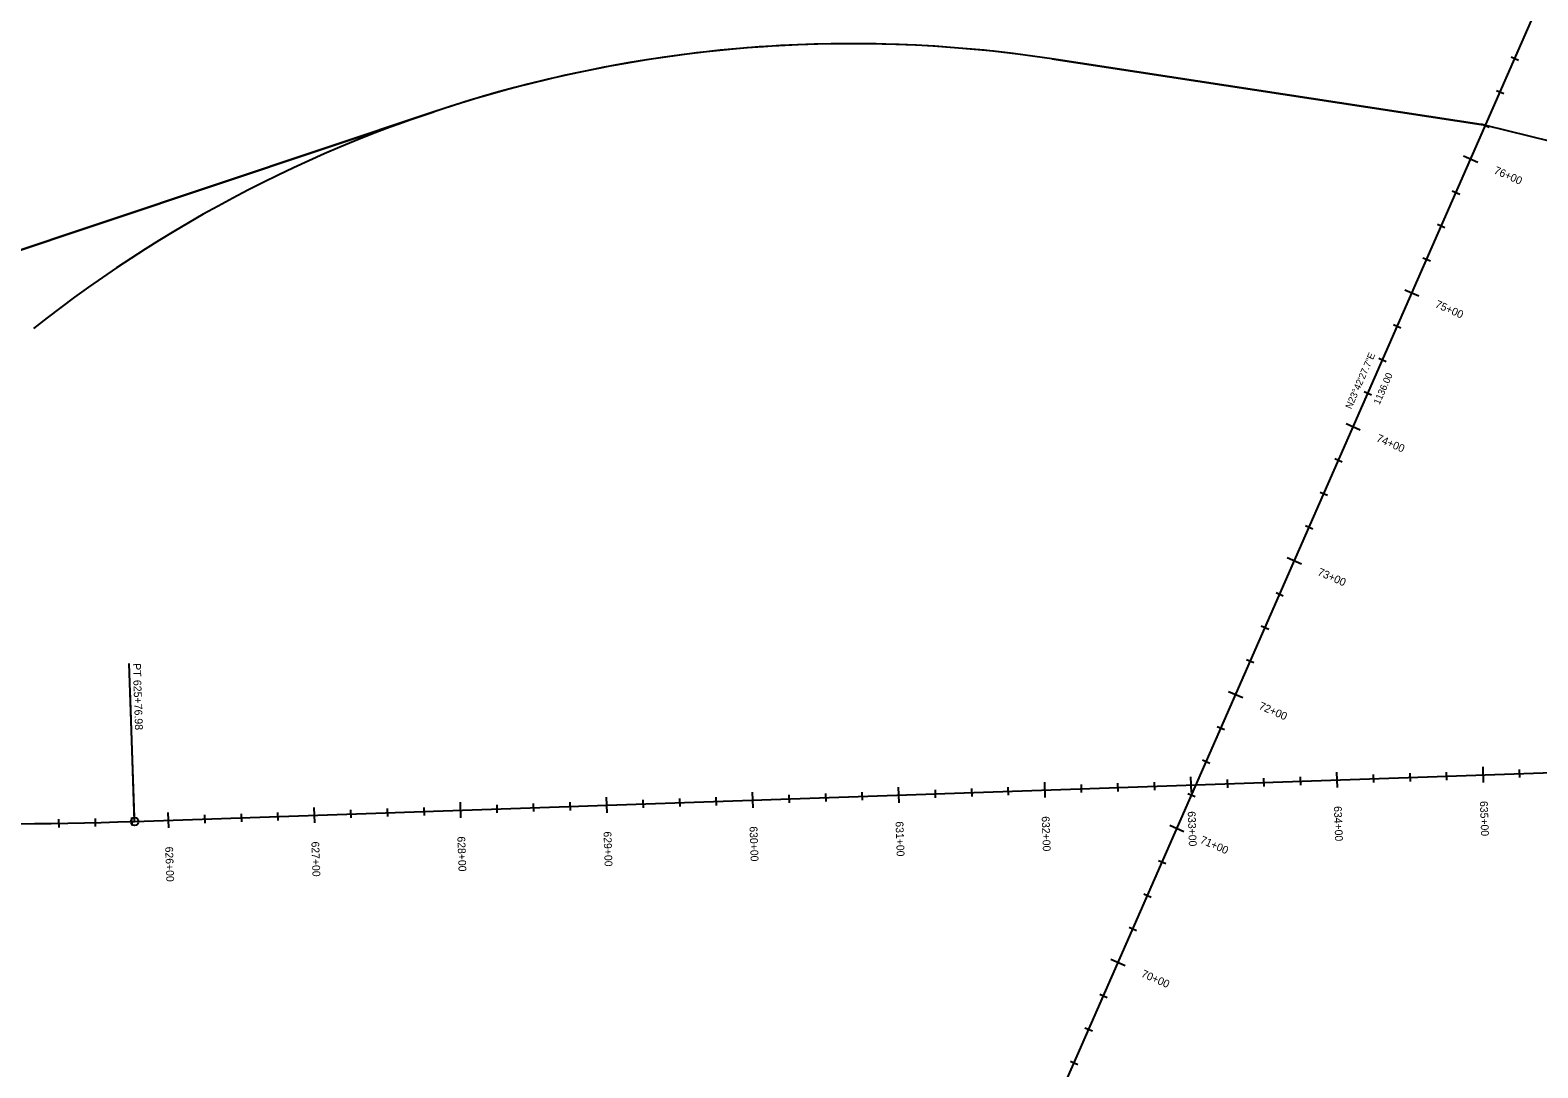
# Model space of a CAD drawing. Extents: x 2307903 to 2339201, y 758183 to 762824.
# Drawn here: x 2320206 to 2321238, y 760043 to 760752 of the extents above; entities that cross this region are included whole.
import ezdxf

# ---------------------------------------------------------------- set-up
doc = ezdxf.new("R2010")
doc.units = 0
for name, color, linetype in [('Default', 7, 'Continuous'), ('E_Terrain_Contour_Imported', 7, 'Continuous'), ('E_Terrain_Contour_Major', 7, 'Continuous'), ('E_Terrain_Flow_Arrows', 7, 'Continuous'), ('E_Terrain_Hole', 7, 'Continuous'), ('E_Terrain_Island', 7, 'Continuous'), ('E_Terrain_Points_High', 7, 'Continuous'), ('E_Terrain_SpotElevation', 7, 'Continuous'), ('Geom_Baseline', 7, 'Continuous')]:
    doc.layers.add(name, color=color, linetype=linetype)

msp = doc.modelspace()

# ---------------------------------------------------------------- linework, layer by layer
at = {"layer": 'Default'}
for p, q in [((2320896.6, 759992.2), (2321353.4, 761032.3)), ((2320896.6, 759992.2), (2321353.4, 761032.3)), ((2320896.6, 759992.2), (2321353.4, 761032.3)), ((2320896.6, 759992.2), (2321353.4, 761032.3)), ((2321219.4, 760734.1), (2321224.5, 760731.9)), ((2321209.4, 760711.2), (2321214.4, 760709)), ((2320482.4, 760696.6), (2319963.7, 760523.2)), ((2320482.4, 760696.6), (2319963.7, 760523.2)), ((2321199.3, 760688.3), (2321204.4, 760686.1)), ((2321186.9, 760666.5), (2321196.6, 760662.2)), ((2321179.2, 760642.6), (2321184.3, 760640.3)), ((2321169.2, 760619.7), (2321174.2, 760617.4)), ((2321159.1, 760596.8), (2321164.2, 760594.6)), ((2321146.7, 760574.9), (2321156.4, 760570.6)), ((2321139, 760551), (2321144.1, 760548.8)), ((2321128.9, 760528.1), (2321134, 760525.9)), ((2321118.9, 760505.2), (2321123.9, 760503)), ((2321106.5, 760483.4), (2321116.2, 760479.1)), ((2321098.8, 760459.4), (2321103.8, 760457.2)), ((2321088.7, 760436.5), (2321093.8, 760434.3)), ((2321078.7, 760413.6), (2321083.7, 760411.4)), ((2321066.3, 760391.8), (2321076, 760387.5)), ((2321058.6, 760367.9), (2321063.6, 760365.6)), ((2320277.7, 760211.3), (2324007.2, 760340.3)), ((2321048.5, 760345), (2321053.6, 760342.8)), ((2321038.5, 760322.1), (2321043.5, 760319.9)), ((2321026.1, 760300.2), (2321035.8, 760296)), ((2321018.4, 760276.3), (2321023.4, 760274.1)), ((2321008.3, 760253.4), (2321013.4, 760251.2)), ((2321200, 760248.6), (2321200.3, 760238)), ((2321225, 760246.9), (2321225.2, 760241.3)), ((2320900.1, 760238.2), (2320900.5, 760227.6)), ((2320925.2, 760236.5), (2320925.4, 760231)), ((2320950.2, 760237.4), (2320950.4, 760231.8)), ((2320975.2, 760238.2), (2320975.4, 760232.7)), ((2321000.1, 760241.7), (2321000.5, 760231)), ((2321025.2, 760239.9), (2321025.3, 760234.4)), ((2321050.1, 760240.8), (2321050.3, 760235.3)), ((2321075.1, 760241.7), (2321075.3, 760236.2)), ((2321100, 760245.1), (2321100.4, 760234.5)), ((2321125.1, 760243.4), (2321125.3, 760237.9)), ((2321150.1, 760244.3), (2321150.3, 760238.7)), ((2321175.1, 760245.1), (2321175.3, 760239.6)), ((2320600.3, 760227.8), (2320600.7, 760217.2)), ((2320625.4, 760226.1), (2320625.6, 760220.6)), ((2320650.4, 760227), (2320650.6, 760221.5)), ((2320675.4, 760227.8), (2320675.6, 760222.3)), ((2320700.3, 760231.3), (2320700.6, 760220.7)), ((2320725.3, 760229.6), (2320725.5, 760224.1)), ((2320750.3, 760230.4), (2320750.5, 760224.9)), ((2320775.3, 760231.3), (2320775.5, 760225.8)), ((2320800.2, 760234.7), (2320800.6, 760224.1)), ((2320825.3, 760233), (2320825.5, 760227.5)), ((2320850.3, 760233.9), (2320850.5, 760228.4)), ((2320875.2, 760234.8), (2320875.4, 760229.2)), ((2320998.3, 760230.5), (2321003.3, 760228.3)), ((2320300.5, 760217.5), (2320300.9, 760206.9)), ((2320325.6, 760215.8), (2320325.8, 760210.2)), ((2320350.6, 760216.6), (2320350.8, 760211.1)), ((2320375.5, 760217.5), (2320375.7, 760212)), ((2320400.4, 760220.9), (2320400.8, 760210.3)), ((2320425.5, 760219.2), (2320425.7, 760213.7)), ((2320450.5, 760220.1), (2320450.7, 760214.6)), ((2320475.5, 760220.9), (2320475.7, 760215.4)), ((2320500.4, 760224.4), (2320500.7, 760213.8)), ((2320525.5, 760222.7), (2320525.6, 760217.1)), ((2320550.4, 760223.5), (2320550.6, 760218)), ((2320575.4, 760224.4), (2320575.6, 760218.9)), ((2320225.7, 760212.8), (2320225.8, 760207.2)), ((2320250.6, 760213.3), (2320250.8, 760207.8)), ((2320275.6, 760214), (2320275.8, 760208.5)), ((2320985.9, 760208.7), (2320995.6, 760204.4)), ((2320978.2, 760184.7), (2320983.2, 760182.5)), ((2320968.1, 760161.9), (2320973.2, 760159.6)), ((2320958.1, 760139), (2320963.1, 760136.7)), ((2320945.7, 760117.1), (2320955.4, 760112.8)), ((2320938, 760093.2), (2320943, 760091)), ((2320927.9, 760070.3), (2320933, 760068.1)), ((2320917.9, 760047.4), (2320922.9, 760045.2))]:
    msp.add_line(p, q, dxfattribs=at)
msp.add_arc((2320175.2, 763175.6), 2966, 264.9144, 271.9805, dxfattribs=at)
at = {"layer": 'E_Terrain_Contour_Imported'}
for p, q in [((2321219.4, 760734.1), (2321224.5, 760731.9)), ((2321209.4, 760711.2), (2321214.4, 760709)), ((2321199.3, 760688.3), (2321204.4, 760686.1)), ((2321179.2, 760642.6), (2321184.3, 760640.3)), ((2321169.2, 760619.7), (2321174.2, 760617.4)), ((2321159.1, 760596.8), (2321164.2, 760594.6)), ((2321139, 760551), (2321144.1, 760548.8)), ((2321128.9, 760528.1), (2321134, 760525.9)), ((2321118.9, 760505.2), (2321123.9, 760503)), ((2321098.8, 760459.4), (2321103.8, 760457.2)), ((2321088.7, 760436.5), (2321093.8, 760434.3)), ((2321078.7, 760413.6), (2321083.7, 760411.4)), ((2321058.6, 760367.9), (2321063.6, 760365.6)), ((2321048.5, 760345), (2321053.6, 760342.8)), ((2321038.5, 760322.1), (2321043.5, 760319.9)), ((2321018.4, 760276.3), (2321023.4, 760274.1)), ((2321008.3, 760253.4), (2321013.4, 760251.2)), ((2321225, 760246.9), (2321225.2, 760241.3)), ((2320925.2, 760236.5), (2320925.4, 760231)), ((2320950.2, 760237.4), (2320950.4, 760231.8)), ((2320975.2, 760238.2), (2320975.4, 760232.7)), ((2321025.2, 760239.9), (2321025.3, 760234.4)), ((2321050.1, 760240.8), (2321050.3, 760235.3)), ((2321075.1, 760241.7), (2321075.3, 760236.2)), ((2321125.1, 760243.4), (2321125.3, 760237.9)), ((2321150.1, 760244.3), (2321150.3, 760238.7)), ((2321175.1, 760245.1), (2321175.3, 760239.6)), ((2320625.4, 760226.1), (2320625.6, 760220.6)), ((2320650.4, 760227), (2320650.6, 760221.5)), ((2320675.4, 760227.8), (2320675.6, 760222.3)), ((2320725.3, 760229.6), (2320725.5, 760224.1)), ((2320750.3, 760230.4), (2320750.5, 760224.9)), ((2320775.3, 760231.3), (2320775.5, 760225.8)), ((2320825.3, 760233), (2320825.5, 760227.5)), ((2320850.3, 760233.9), (2320850.5, 760228.4)), ((2320875.2, 760234.8), (2320875.4, 760229.2)), ((2320998.3, 760230.5), (2321003.3, 760228.3)), ((2320325.6, 760215.8), (2320325.8, 760210.2)), ((2320350.6, 760216.6), (2320350.8, 760211.1)), ((2320375.5, 760217.5), (2320375.7, 760212)), ((2320425.5, 760219.2), (2320425.7, 760213.7)), ((2320450.5, 760220.1), (2320450.7, 760214.6)), ((2320475.5, 760220.9), (2320475.7, 760215.4)), ((2320525.5, 760222.7), (2320525.6, 760217.1)), ((2320550.4, 760223.5), (2320550.6, 760218)), ((2320575.4, 760224.4), (2320575.6, 760218.9)), ((2320225.7, 760212.8), (2320225.8, 760207.2)), ((2320250.6, 760213.3), (2320250.8, 760207.8)), ((2320275.6, 760214), (2320275.8, 760208.5)), ((2320978.2, 760184.7), (2320983.2, 760182.5)), ((2320968.1, 760161.9), (2320973.2, 760159.6)), ((2320958.1, 760139), (2320963.1, 760136.7)), ((2320938, 760093.2), (2320943, 760091)), ((2320927.9, 760070.3), (2320933, 760068.1)), ((2320917.9, 760047.4), (2320922.9, 760045.2))]:
    msp.add_line(p, q, dxfattribs=at)
at = {"layer": 'E_Terrain_Hole'}
for p, q in [((2321201.9, 760687.3), (2320905.3, 760732.7)), ((2320905.3, 760732.7), (2321201.9, 760687.3)), ((2319963.7, 760523.2), (2320482.4, 760696.6))]:
    msp.add_line(p, q, dxfattribs=at)
for end in [128.329, 108.4803, 108.4803]:
    msp.add_arc((2320768.6, 759840.1), 903, 81.2923, end, dxfattribs=at)
at = {"layer": 'E_Terrain_Island'}
for p, q in [((2321186.9, 760666.5), (2321196.6, 760662.2)), ((2321146.7, 760574.9), (2321156.4, 760570.6)), ((2321106.5, 760483.4), (2321116.2, 760479.1)), ((2321066.3, 760391.8), (2321076, 760387.5)), ((2321026.1, 760300.2), (2321035.8, 760296)), ((2321200, 760248.6), (2321200.3, 760238)), ((2320900.1, 760238.2), (2320900.5, 760227.6)), ((2321000.1, 760241.7), (2321000.5, 760231)), ((2321100, 760245.1), (2321100.4, 760234.5)), ((2320600.3, 760227.8), (2320600.7, 760217.2)), ((2320700.3, 760231.3), (2320700.6, 760220.7)), ((2320800.2, 760234.7), (2320800.6, 760224.1)), ((2320300.5, 760217.5), (2320300.9, 760206.9)), ((2320400.4, 760220.9), (2320400.8, 760210.3)), ((2320500.4, 760224.4), (2320500.7, 760213.8)), ((2320985.9, 760208.7), (2320995.6, 760204.4)), ((2320945.7, 760117.1), (2320955.4, 760112.8))]:
    msp.add_line(p, q, dxfattribs=at)
at = {"layer": 'E_Terrain_Points_High'}
msp.add_line((2320277.6, 760214), (2320273.9, 760319.3), dxfattribs=at)
at = {"layer": 'E_Terrain_SpotElevation'}
for p, q in [((2320273.9, 760319.3), (2320273.9, 760319.3)), ((2320277.7, 760211.3), (2320274.6, 760301.3)), ((2320277.7, 760211.3), (2320277.7, 760211.3))]:
    msp.add_line(p, q, dxfattribs=at)
msp.add_circle((2320277.7, 760211.3), 2.67, dxfattribs=at)
msp.add_circle((2320277.7, 760211.3), 2.67, dxfattribs=at)
at = {"layer": 'Geom_Baseline'}
for p, q in [((2320896.6, 759992.2), (2321353.4, 761032.3)), ((2321201.9, 760687.3), (2322018.2, 760488)), ((2320277.7, 760211.3), (2324007.2, 760340.3))]:
    msp.add_line(p, q, dxfattribs=at)
msp.add_arc((2320175.2, 763175.6), 2966, 264.9144, 271.9805, dxfattribs=at)

# ---------------------------------------------------------------- texts
at = {"layer": 'E_Terrain_Contour_Major'}
for s, rotation, p in [('76+00', 336.2923, (2321207.2, 760654.6)), ('75+00', 336.2923, (2321167, 760563.1)), ('74+00', 336.2923, (2321126.8, 760471.5)), ('73+00', 336.2923, (2321086.6, 760380)), ('72+00', 336.2923, (2321046.4, 760288.4)), ('633+00', 271.9805, (2320998.2, 760218.2)), ('634+00', 271.9805, (2321098.2, 760221.7)), ('635+00', 271.9805, (2321198.1, 760225.2)), ('630+00', 271.9805, (2320698.4, 760207.9)), ('631+00', 271.9805, (2320798.3, 760211.3)), ('632+00', 271.9805, (2320898.3, 760214.8)), ('627+00', 271.9805, (2320398.6, 760197.5)), ('628+00', 271.9805, (2320498.5, 760201)), ('629+00', 271.9805, (2320598.5, 760204.4)), ('71+00', 336.2923, (2321006.2, 760196.8)), ('626+00', 271.9805, (2320298.6, 760194)), ('70+00', 336.2923, (2320965.9, 760105.3))]:
    msp.add_text(s, height=5.34, rotation=rotation, dxfattribs=at).set_placement(p)
at = {"layer": 'E_Terrain_Flow_Arrows'}
for s, height, p in [('N23°42\'27.7"E', 4.724, (2321110.1, 760492.9)), ('1136.00', 4.72, (2321129.4, 760495.9))]:
    msp.add_text(s, height=height, rotation=66.2923, dxfattribs=at).set_placement(p)
at = {"layer": 'E_Terrain_SpotElevation'}
for s, p in [('PT', (2320276.5, 760319.4)), ('625+76.98', (2320276.8, 760308))]:
    msp.add_text(s, height=5.4, rotation=271.9805, dxfattribs=at).set_placement(p)

doc.saveas('drawing.dxf')
